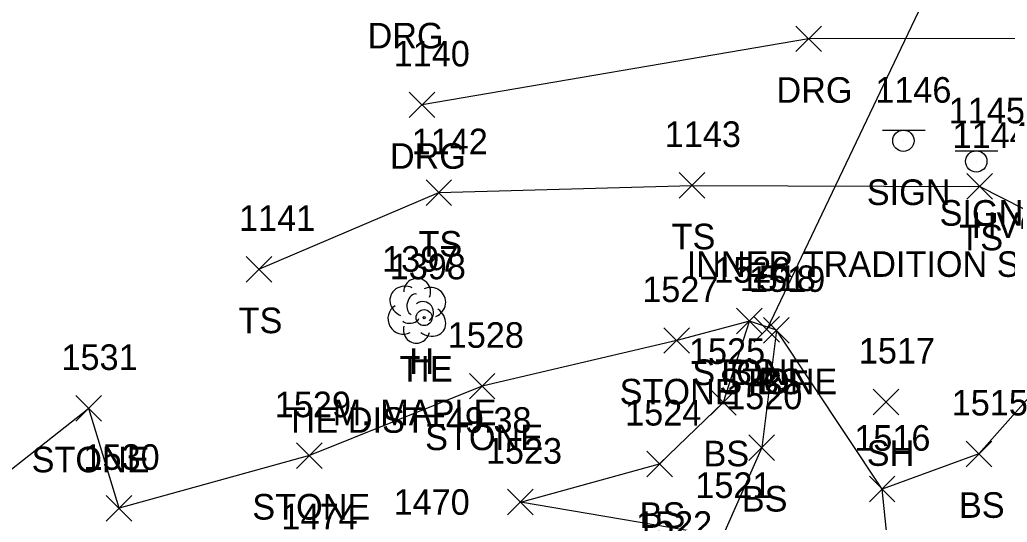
# Model space of a CAD drawing. Extents: x 1599840 to 1601211, y 518904 to 521989.
# Drawn here: x 1600737.9 to 1600815, y 521314.2 to 521353.5 of the extents above; entities that cross this region are included whole.
import ezdxf

# ---------------------------------------------------------------- set-up
doc = ezdxf.new("R2010")
doc.units = 0
for name, color, linetype in [('C_A', 7, 'Continuous'), ('C_C', 7, 'Continuous'), ('C_I', 7, 'Continuous'), ('CBP', 7, 'Continuous'), ('D_A', 7, 'Continuous'), ('D_I', 7, 'Continuous'), ('D_TIC', 7, 'Continuous'), ('DCP', 7, 'Continuous'), ('L_A', 7, 'Continuous'), ('L_C', 7, 'Continuous'), ('L_I', 7, 'Continuous'), ('L_TIC', 7, 'Continuous'), ('LASF', 7, 'Continuous'), ('LELB', 7, 'Continuous'), ('LTD', 7, 'Continuous'), ('R_A', 7, 'Continuous'), ('R_I', 7, 'Continuous'), ('R_TIC', 7, 'Continuous'), ('RDG', 7, 'Continuous'), ('S_A', 7, 'Continuous'), ('S_C', 7, 'Continuous'), ('S_I', 7, 'Continuous'), ('SSGN', 7, 'Continuous')]:
    doc.layers.add(name, color=color, linetype=linetype)

msp = doc.modelspace()

# ---------------------------------------------------------------- linework, layer by layer
at = {"layer": 'CBP'}
for radius in [0.625, 0.0833]:
    msp.add_circle((1600769.462, 521330.187), radius, dxfattribs=at)
at = {"layer": 'D_TIC'}
for points in [[(1600795.227, 521328.266), (1600797.227, 521330.266)], [(1600797.227, 521328.266), (1600795.227, 521330.266)]]:
    msp.add_lwpolyline(points, dxfattribs=at)
at = {"layer": 'DCP'}
msp.add_lwpolyline([(1600822.553, 521384.532), (1600796.227, 521329.266)], dxfattribs=at)
at = {"layer": 'L_TIC'}
for points in [[(1600769.612, 521338.958), (1600771.612, 521340.958)], [(1600771.612, 521338.958), (1600769.612, 521340.958)], [(1600789.384, 521339.53), (1600791.384, 521341.53)], [(1600791.384, 521339.53), (1600789.384, 521341.53)], [(1600811.861, 521339.452), (1600813.861, 521341.452)], [(1600813.861, 521339.452), (1600811.861, 521341.452)], [(1600755.563, 521332.971), (1600757.563, 521334.971)], [(1600757.563, 521332.971), (1600755.563, 521334.971)], [(1600793.865, 521328.922), (1600795.865, 521330.922)], [(1600795.865, 521328.922), (1600793.865, 521330.922)], [(1600793.865, 521328.922), (1600795.865, 521330.922)], [(1600795.865, 521328.922), (1600793.865, 521330.922)], [(1600795.978, 521328.204), (1600797.978, 521330.204)], [(1600797.978, 521328.204), (1600795.978, 521330.204)], [(1600795.978, 521328.204), (1600797.978, 521330.204)], [(1600797.978, 521328.204), (1600795.978, 521330.204)], [(1600788.19, 521327.403), (1600790.19, 521329.403)], [(1600790.19, 521327.403), (1600788.19, 521329.403)], [(1600772.997, 521323.831), (1600774.997, 521325.831)], [(1600774.997, 521323.831), (1600772.997, 521325.831)], [(1600791.84, 521322.569), (1600793.84, 521324.569)], [(1600793.84, 521322.569), (1600791.84, 521324.569)], [(1600804.545, 521322.603), (1600806.545, 521324.603)], [(1600806.545, 521322.603), (1600804.545, 521324.603)], [(1600742.26, 521322.098), (1600744.26, 521324.098)], [(1600744.26, 521322.098), (1600742.26, 521324.098)], [(1600794.834, 521319.03), (1600796.834, 521321.03)], [(1600796.834, 521319.03), (1600794.834, 521321.03)], [(1600759.497, 521318.404), (1600761.497, 521320.404)], [(1600761.497, 521318.404), (1600759.497, 521320.404)], [(1600811.796, 521318.539), (1600813.796, 521320.539)], [(1600813.796, 521318.539), (1600811.796, 521320.539)], [(1600786.857, 521317.753), (1600788.857, 521319.753)], [(1600788.857, 521317.753), (1600786.857, 521319.753)], [(1600804.239, 521315.786), (1600806.239, 521317.786)], [(1600806.239, 521315.786), (1600804.239, 521317.786)], [(1600804.239, 521315.786), (1600806.239, 521317.786)], [(1600806.239, 521315.786), (1600804.239, 521317.786)], [(1600744.632, 521314.291), (1600746.632, 521316.291)], [(1600746.632, 521314.291), (1600744.632, 521316.291)], [(1600775.979, 521314.771), (1600777.979, 521316.771)], [(1600777.979, 521314.771), (1600775.979, 521316.771)]]:
    msp.add_lwpolyline(points, dxfattribs=at)
at = {"layer": 'LASF'}
msp.add_lwpolyline([(1600788.504, 521302.133), (1600797.248, 521300.149), (1600801.203, 521300.015), (1600804.381, 521299.912), (1600806.428, 521305.176), (1600805.239, 521316.786), (1600796.978, 521329.204), (1600794.865, 521329.922), (1600789.19, 521328.403), (1600773.997, 521324.831), (1600760.497, 521319.404), (1600745.632, 521315.291), (1600743.26, 521323.098), (1600732.014, 521314.218), (1600727.669, 521298.755)], dxfattribs=at)
at = {"layer": 'LELB'}
for points in [[(1600756.563, 521333.971), (1600770.612, 521339.958), (1600790.384, 521340.53), (1600812.861, 521340.452), (1600821.545, 521336.048), (1600828.426, 521332.182)], [(1600796.978, 521329.204), (1600795.834, 521320.03), (1600792.769, 521313.092), (1600776.979, 521315.771), (1600787.857, 521318.753), (1600792.84, 521323.569), (1600794.865, 521329.922)], [(1600806.428, 521305.176), (1600817.079, 521310.295), (1600825.263, 521317.394), (1600823.051, 521319.829), (1600819.351, 521326.934), (1600812.796, 521319.539), (1600805.239, 521316.786)]]:
    msp.add_lwpolyline(points, dxfattribs=at)
at = {"layer": 'LTD'}
msp.add_line((1600768.873, 521330.778), (1600768.873, 521330.778), dxfattribs=at)
msp.add_line((1600768.873, 521330.778), (1600768.873, 521330.778), dxfattribs=at)
msp.add_arc((1600768.92, 521332.212), 1.047, 335.52715, 180.95627, dxfattribs=at)
for centre, major_axis, ratio, start_param, end_param in [((1600768.081, 521331.445), (1.21, -0.512), 0.895232, 1.570796, 4.712389), ((1600769.915, 521331.362), (-1.141, -0.483), 0.949671, 1.570796, 4.712389), ((1600768.665, 521331.237), (-0.208, -0.792), 0.645439, 3.141593, 6.283185), ((1600769.373, 521330.612), (-0.5, 0.667), 0.989748, 3.141593, 6.283185), ((1600767.79, 521330.07), (0.584, -1.042), 0.959034, 3.141593, 6.283185), ((1600769.873, 521329.945), (-1.09, 0.792), 0.841452, 1.570796, 4.712389), ((1600768.415, 521330.028), (-0.625, -0.083), 0.423636, 0, 3.141593), ((1600768.873, 521329.278), (0.265, 1.061), 0.942809, 1.570796, 4.712389)]:
    msp.add_ellipse(centre, major_axis=major_axis, ratio=ratio, start_param=start_param, end_param=end_param, dxfattribs=at)
at = {"layer": 'R_TIC'}
for points in [[(1600798.493, 521350.982), (1600800.493, 521352.982)], [(1600800.493, 521350.982), (1600798.493, 521352.982)], [(1600768.296, 521345.823), (1600770.296, 521347.823)], [(1600770.296, 521345.823), (1600768.296, 521347.823)]]:
    msp.add_lwpolyline(points, dxfattribs=at)
at = {"layer": 'RDG'}
msp.add_lwpolyline([(1600846.401, 521325.716), (1600843.17, 521332.508), (1600837.091, 521339.835), (1600826.46, 521347.89), (1600817.658, 521352.007), (1600799.493, 521351.982), (1600769.296, 521346.823)], dxfattribs=at)
at = {"layer": 'SSGN'}
for p, q in [((1600805.252, 521344.845), (1600808.586, 521344.845)), ((1600806.899, 521344.012), (1600806.899, 521344.012)), ((1600810.94, 521343.228), (1600814.273, 521343.228)), ((1600812.586, 521342.395), (1600812.586, 521342.395))]:
    msp.add_line(p, q, dxfattribs=at)
for centre in [(1600806.899, 521344.012), (1600812.586, 521342.395)]:
    msp.add_circle(centre, 0.833, dxfattribs=at)

# ---------------------------------------------------------------- texts
at = {"layer": 'C_A'}
for s, p in [('HVCTRL', (1600812.245, 521336.423)), ('TIE', (1600767.541, 521325.187))]:
    msp.add_text(s, height=2, dxfattribs=at).set_placement(p)
at = {"layer": 'C_C'}
msp.add_text('TIE DIST=49.38', height=2, dxfattribs=at).set_placement((1600758.597, 521321.187))
at = {"layer": 'C_I'}
msp.add_text('1398', height=2, dxfattribs=at).set_placement((1600766.77, 521333.187))
at = {"layer": 'D_A'}
msp.add_text('P', height=2, dxfattribs=at).set_placement((1600795.605, 521324.266))
at = {"layer": 'D_I'}
msp.add_text('1518', height=2, dxfattribs=at).set_placement((1600794.102, 521332.266))
at = {"layer": 'L_A'}
for s, p in [('TS', (1600769.021, 521334.958)), ('TS', (1600788.794, 521335.53)), ('TS', (1600811.27, 521335.452)), ('TS', (1600754.973, 521328.971)), ('H', (1600768.306, 521325.778)), ('STONE', (1600790.408, 521324.922)), ('BS', (1600793.306, 521324.922)), ('STONE', (1600792.521, 521324.204)), ('BS', (1600795.419, 521324.204)), ('STONE', (1600784.733, 521323.403)), ('STONE', (1600769.541, 521319.831)), ('STONE', (1600738.803, 521318.098)), ('BS', (1600791.281, 521318.569)), ('SH', (1600804.033, 521318.603)), ('BS', (1600794.275, 521315.03)), ('STONE', (1600756.041, 521314.404)), ('BS', (1600811.237, 521314.539)), ('BS', (1600786.298, 521313.753))]:
    msp.add_text(s, height=2, dxfattribs=at).set_placement(p)
at = {"layer": 'L_C'}
msp.add_text('M. MAPLE', height=2, dxfattribs=at).set_placement((1600762.322, 521321.778))
at = {"layer": 'L_I'}
for s, p in [('1143', (1600788.259, 521343.53)), ('1144', (1600810.735, 521343.452)), ('1142', (1600768.486, 521342.958)), ('1141', (1600755.004, 521336.971)), ('1397', (1600766.18, 521333.778)), ('1526', (1600792.117, 521332.922)), ('1526', (1600792.117, 521332.922)), ('1519', (1600794.844, 521332.204)), ('1519', (1600794.844, 521332.204)), ('1527', (1600786.497, 521331.403)), ('1528', (1600771.305, 521327.831)), ('1525', (1600790.147, 521326.569)), ('1517', (1600803.419, 521326.603)), ('1531', (1600741.134, 521326.098)), ('1520', (1600793.055, 521323.03)), ('1529', (1600757.797, 521322.404)), ('1515', (1600810.67, 521322.539)), ('1524', (1600785.164, 521321.753)), ('1516', (1600803.058, 521319.786)), ('1516', (1600803.058, 521319.786)), ('1523', (1600774.286, 521318.771)), ('1530', (1600742.853, 521318.291)), ('1521', (1600790.643, 521316.092)), ('1470', (1600767.074, 521314.777)), ('1474', (1600758.317, 521313.636)), ('1522', (1600786.009, 521313.057))]:
    msp.add_text(s, height=2, dxfattribs=at).set_placement(p)
at = {"layer": 'R_A'}
for p in [(1600765.043, 521351.23), (1600796.981, 521346.982), (1600766.785, 521341.823)]:
    msp.add_text('DRG', height=2, dxfattribs=at).set_placement(p)
at = {"layer": 'R_I'}
msp.add_text('1140', height=2, dxfattribs=at).set_placement((1600767.084, 521349.823))
at = {"layer": 'S_A'}
for p in [(1600804.037, 521338.992), (1600809.724, 521337.375)]:
    msp.add_text('SIGN', height=2, dxfattribs=at).set_placement(p)
at = {"layer": 'S_C'}
msp.add_text('INNER TRADITION SOLAR FARM', height=2, dxfattribs=at).set_placement((1600789.969, 521333.375))
at = {"layer": 'S_I'}
for s, p in [('1146', (1600804.699, 521346.992)), ('1145', (1600810.441, 521345.375))]:
    msp.add_text(s, height=2, dxfattribs=at).set_placement(p)

doc.saveas('drawing.dxf')
